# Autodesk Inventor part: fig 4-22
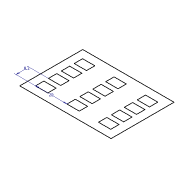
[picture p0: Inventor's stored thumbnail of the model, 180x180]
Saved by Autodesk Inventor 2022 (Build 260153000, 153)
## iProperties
Created: 2004-05
Part Number: fig 4-22
Document SubType Name: Modeling
Designer: CADCIM Technologies
Manufacturer: Standard
Standards Organization: Custom
Density: 1 g/cm^3
Material: Generic
Appearance: Default
Author: CADCIM Technologies
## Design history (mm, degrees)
sketch "Sketch1"
  geometry: L1 (7.752, 6.176)-(65.752, 6.176); L2 (65.752, 6.176)-(65.752, 46.176); L3 (65.752, 46.176)-(7.752, 46.176); L4 (7.752, 46.176)-(7.752, 6.176); L5 (12.752, 11.176)-(20.543, 11.176); L6 (20.543, 11.176)-(20.543, 16.473); L7 (20.543, 16.473)-(12.752, 16.473); L8 (12.752, 16.473)-(12.752, 11.176); L9 (32.752, 11.176)-(40.543, 11.176); L10 (40.543, 11.176)-(40.543, 16.473); L11 (40.543, 16.473)-(32.752, 16.473); L12 (32.752, 16.473)-(32.752, 11.176); L13 (52.752, 11.176)-(60.543, 11.176); L14 (60.543, 11.176)-(60.543, 16.473); L15 (60.543, 16.473)-(52.752, 16.473); L16 (52.752, 16.473)-(52.752, 11.176); L17 (12.752, 19.376)-(20.543, 19.376); L18 (20.543, 19.376)-(20.543, 24.673); L19 (20.543, 24.673)-(12.752, 24.673); L20 (12.752, 24.673)-(12.752, 19.376); L21 (32.752, 19.376)-(40.543, 19.376); L22 (40.543, 19.376)-(40.543, 24.673); L23 (40.543, 24.673)-(32.752, 24.673); L24 (32.752, 24.673)-(32.752, 19.376); L25 (52.752, 19.376)-(60.543, 19.376); L26 (60.543, 19.376)-(60.543, 24.673); L27 (60.543, 24.673)-(52.752, 24.673); L28 (52.752, 24.673)-(52.752, 19.376); L29 (12.752, 27.576)-(20.543, 27.576); L30 (20.543, 27.576)-(20.543, 32.873); L31 (20.543, 32.873)-(12.752, 32.873); L32 (12.752, 32.873)-(12.752, 27.576); L33 (32.752, 27.576)-(40.543, 27.576); L34 (40.543, 27.576)-(40.543, 32.873); L35 (40.543, 32.873)-(32.752, 32.873); L36 (32.752, 32.873)-(32.752, 27.576); L37 (52.752, 27.576)-(60.543, 27.576); L38 (60.543, 27.576)-(60.543, 32.873); L39 (60.543, 32.873)-(52.752, 32.873); L40 (52.752, 32.873)-(52.752, 27.576); L41 (12.752, 35.776)-(20.543, 35.776); L42 (20.543, 35.776)-(20.543, 41.073); L43 (20.543, 41.073)-(12.752, 41.073); L44 (12.752, 41.073)-(12.752, 35.776); L45 (32.752, 35.776)-(40.543, 35.776); L46 (40.543, 35.776)-(40.543, 41.073); L47 (40.543, 41.073)-(32.752, 41.073); L48 (32.752, 41.073)-(32.752, 35.776); L49 (52.752, 35.776)-(60.543, 35.776); L50 (60.543, 35.776)-(60.543, 41.073); L51 (60.543, 41.073)-(52.752, 41.073); L52 (52.752, 41.073)-(52.752, 35.776)
  constraints: 104 end point, 4 parallel, 3 horizontal, 2 perpendicular, 1 vertical, 88 other
  dimensions: "d14" = 20 distance of L5.start L9.start; "d17" = 8.2 distance of L5.start L17.start
